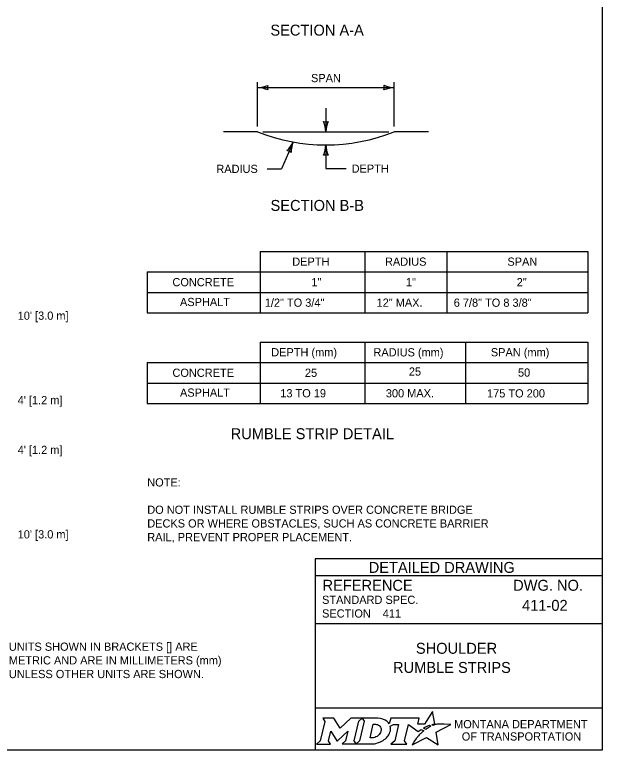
# Model space of a CAD drawing. Extents: x 49991.4 to 50021, y 49987.6 to 50011.4.
# Drawn here: x 50012.45 to 50016.75, y 49987.8 to 49993.18 of the extents above; entities that cross this region are included whole.
import ezdxf

# ---------------------------------------------------------------- set-up
doc = ezdxf.new("R2010")
doc.units = 0
for name, color, linetype in [('Default', 7, 'Continuous'), ('Level 1', 7, 'Continuous'), ('Level 2', 7, 'Continuous'), ('Level 3', 7, 'Continuous'), ('Level 5', 7, 'Continuous')]:
    doc.layers.add(name, color=color, linetype=linetype)

msp = doc.modelspace()

# ---------------------------------------------------------------- linework, layer by layer
at = {"layer": 'Default'}
for points in [[(50015.5126, 49987.9811), (50015.5023, 49987.9867), (50015.5139, 49987.9895), (50015.5255, 49987.9915), (50015.5081, 49988.0816), (50015.4486, 49987.9903), (50015.4013, 49987.9896), (50015.4116, 49988.0337), (50015.2024, 49988.0338), (50015.1923, 49987.9913), (50015.1865, 49987.9996)], [(50014.7056, 49988.0338), (50014.7197, 49988.0104), (50014.6862, 49987.8671), (50014.6605, 49987.8446), (50014.7621, 49987.8446), (50014.7486, 49987.8674), (50014.7648, 49987.9375), (50014.8085, 49987.8685), (50014.8138, 49987.8685), (50014.8889, 49987.938), (50014.8725, 49987.8669), (50014.8478, 49987.8449), (50014.9494, 49987.8449), (50014.9356, 49987.8682), (50014.9688, 49988.0106)], [(50014.9688, 49988.0106), (50014.9941, 49988.0338), (50014.9117, 49988.0338), (50014.8321, 49987.9608), (50014.7876, 49988.0335), (50014.7056, 49988.0338)], [(50015.1077, 49988.0338), (50014.9941, 49988.0338), (50015.0088, 49988.0109), (50014.9749, 49987.8671), (50014.9494, 49987.8449), (50015.06, 49987.8449)], [(50015.1317, 49987.9471), (50015.1305, 49987.939), (50015.1273, 49987.9297), (50015.1231, 49987.9215), (50015.1175, 49987.914), (50015.111, 49987.9071), (50015.1031, 49987.9008), (50015.0948, 49987.8961), (50015.0857, 49987.8922), (50015.0766, 49987.8899), (50015.0674, 49987.889), (50015.0515, 49987.889), (50015.0751, 49987.989), (50015.0911, 49987.989), (50015.0987, 49987.9884), (50015.1063, 49987.9865), (50015.1129, 49987.9835), (50015.119, 49987.9793), (50015.1238, 49987.9743), (50015.1275, 49987.9683), (50015.1302, 49987.9621), (50015.1318, 49987.9547), (50015.1318, 49987.9517), (50015.1317, 49987.9471)], [(50015.3882, 49987.8843), (50015.3729, 49987.8599), (50015.3682, 49987.8524), (50015.3624, 49987.8438), (50015.3601, 49987.8395), (50015.4654, 49987.8926), (50015.5493, 49987.8375), (50015.5362, 49987.9302), (50015.6431, 49987.9886), (50015.5938, 49987.9894), (50015.5637, 49987.9898), (50015.5429, 49987.9901), (50015.5361, 49987.9886), (50015.5312, 49987.9874), (50015.5228, 49987.9851), (50015.5126, 49987.9811)], [(50015.1991, 49987.9747), (50015.2237, 49987.9878), (50015.2606, 49987.9878), (50015.232, 49987.8673), (50015.2045, 49987.8446), (50015.3207, 49987.8446), (50015.3037, 49987.8675), (50015.3319, 49987.9877), (50015.4032, 49987.936), (50015.4243, 49987.9511), (50015.444, 49987.9402)], [(50015.4622, 49987.9535), (50015.4598, 49987.9518), (50015.4415, 49987.9614), (50015.4518, 49987.9671), (50015.4559, 49987.9693), (50015.4645, 49987.9733), (50015.4702, 49987.9759), (50015.4781, 49987.9789), (50015.4854, 49987.9816), (50015.4972, 49987.9742), (50015.4932, 49987.9721), (50015.4886, 49987.9696), (50015.4844, 49987.9674), (50015.4794, 49987.9645), (50015.4775, 49987.9634), (50015.4748, 49987.9618), (50015.4723, 49987.9604), (50015.47, 49987.9588), (50015.4674, 49987.957), (50015.4647, 49987.9552), (50015.4622, 49987.9535)], [(50015.4021, 49987.9004), (50015.4021, 49987.9004)], [(50015.1057, 49987.8522), (50015.1141, 49987.8548), (50015.1271, 49987.8602), (50015.1475, 49987.8712)]]:
    msp.add_lwpolyline(points, dxfattribs=at)
for centre, radius, start, end in [((50015.1308, 49987.9554), 0.0709, 339.5329, 15.8582), ((50015.0868, 49987.9727), 0.1183, 300.9103, 339.1383)]:
    msp.add_arc(centre, radius, start, end, dxfattribs=at)
for centre, major_axis, ratio, start_param, end_param in [((50015.1056, 49987.9864), (0.0834, -0.0037), 0.568097, 0.61298, 1.570796), ((50015.1612, 49987.9937), (0.0361, -0.0295), 0.469099, 1.225588, 1.570796), ((50015.4329, 49987.9305), (-0.0112, -0.0097), 0.021651, 3.157348, 6.283185), ((50015.3952, 49987.8923), (-0.00694, -0.00806), 0.008222, 0, 3.137361), ((50015.4119, 49987.9106), (-0.0098, -0.0102), 0.016458, 3.141593, 6.279097), ((50015.0603, 49987.9932), (0, 0.1484), 0.987302, 3.139398, 3.456847)]:
    msp.add_ellipse(centre, major_axis=major_axis, ratio=ratio, start_param=start_param, end_param=end_param, dxfattribs=at)
at = {"layer": 'Level 1'}
for p, q in [((50014.2284, 49992.3211), (50013.9784, 49992.3211)), ((50015.4784, 49992.3211), (50015.2284, 49992.3211))]:
    msp.add_line(p, q, dxfattribs=at)
msp.add_lwpolyline([(49999.3835, 49998.9992), (50016.7501, 49998.9992), (50016.7501, 49987.7988), (49999.3835, 49987.7988)], close=True, dxfattribs=at)
msp.add_arc((50014.7283, 49993.5894), 1.3633, 248.4841, 291.5159, dxfattribs=at)
at = {"layer": 'Level 2'}
for p, q in [((50014.2469, 49991.4473), (50016.6435, 49991.4473)), ((50014.2469, 49991.4473), (50014.2469, 49990.9973)), ((50015.0139, 49991.4473), (50015.0139, 49990.9973)), ((50015.6139, 49991.4473), (50015.6139, 49990.9973)), ((50016.6435, 49991.4473), (50016.6435, 49990.9973)), ((50013.4219, 49991.2973), (50013.4219, 49990.9973)), ((50013.4219, 49991.2973), (50014.2469, 49991.2973)), ((50014.2469, 49991.2973), (50016.6435, 49991.2973)), ((50014.2469, 49991.2973), (50016.1469, 49991.2973)), ((50014.2469, 49991.2973), (50016.1469, 49991.2973)), ((50013.4219, 49991.1473), (50016.6435, 49991.1473)), ((50014.2469, 49991.1473), (50016.1469, 49991.1473)), ((50013.4219, 49990.9973), (50016.6435, 49990.9973)), ((50014.2469, 49990.9973), (50016.1469, 49990.9973)), ((50014.2469, 49990.7846), (50016.6435, 49990.7846)), ((50014.2469, 49990.7846), (50014.2469, 49990.3346)), ((50015.0139, 49990.7846), (50015.0139, 49990.3346)), ((50015.7508, 49990.7846), (50015.7508, 49990.3346)), ((50016.6435, 49990.7846), (50016.6435, 49990.3346)), ((50013.4219, 49990.6346), (50013.4219, 49990.3346)), ((50013.4219, 49990.6346), (50016.6435, 49990.6346)), ((50013.4219, 49990.4846), (50016.6435, 49990.4846)), ((50013.4219, 49990.3346), (50016.6435, 49990.3346))]:
    msp.add_line(p, q, dxfattribs=at)
at = {"layer": 'Level 3'}
for p, q in [((50014.2284, 49992.3611), (50014.2284, 49992.6849)), ((50015.2284, 49992.3611), (50015.2284, 49992.6849)), ((50014.2284, 49992.6449), (50015.2284, 49992.6449)), ((50014.7284, 49992.4945), (50014.7284, 49992.3211)), ((50014.2683, 49992.3211), (50015.1883, 49992.3211)), ((50014.4888, 49992.2473), (50014.4043, 49992.0508)), ((50014.7284, 49992.2261), (50014.7284, 49992.0527)), ((50014.2988, 49992.0508), (50014.4043, 49992.0508)), ((50014.7284, 49992.0527), (50014.8766, 49992.0527))]:
    msp.add_line(p, q, dxfattribs=at)
for centre, radius, start, end in [((50014.2169, 49992.8776), 0.233, 272.8273, 292.0772), ((50014.2192, 49992.4228), 0.2223, 67.456, 87.6395), ((50014.3566, 49992.6449), 0.0548, 162.1388, 197.8612), ((50015.2376, 49992.8671), 0.2223, 247.456, 267.6395), ((50015.1002, 49992.6449), 0.0548, 342.1388, 17.8612), ((50015.2399, 49992.4122), 0.233, 92.8273, 112.0772), ((50014.7284, 49992.4493), 0.0548, 252.1388, 287.8612), ((50014.4957, 49992.3096), 0.233, 2.8273, 22.0772), ((50014.9505, 49992.312), 0.2223, 157.456, 177.6395), ((50014.2883, 49992.3435), 0.2223, 314.1908, 334.3743), ((50014.7071, 49992.166), 0.233, 159.5621, 178.8119), ((50014.5063, 49992.2353), 0.2223, 337.456, 357.6395), ((50014.9611, 49992.2376), 0.233, 182.8273, 202.0772), ((50014.4382, 49992.1296), 0.0548, 48.8736, 84.5959), ((50014.7284, 49992.0979), 0.0548, 72.1388, 107.8612)]:
    msp.add_arc(centre, radius, start, end, dxfattribs=at)
at = {"layer": 'Level 5'}
for p, q in [((50016.7501, 49989.1988), (50014.6501, 49989.1988)), ((50014.6501, 49989.1988), (50014.6501, 49987.7988)), ((50016.7501, 49989.0738), (50014.6501, 49989.0738)), ((50016.3862, 49988.8587), (50016.3862, 49988.8587)), ((50015.1444, 49988.7993), (50015.1444, 49988.7993)), ((50016.7501, 49988.7238), (50014.6501, 49988.7238)), ((50015.7001, 49988.4747), (50015.7001, 49988.4747)), ((50016.7501, 49988.1057), (50014.6501, 49988.1057))]:
    msp.add_line(p, q, dxfattribs=at)

# ---------------------------------------------------------------- texts
at = {"layer": 'Default'}
for s, p in [('MONTANA DEPARTMENT', (50015.6663, 49987.96)), ('OF TRANSPORTATION', (50015.7225, 49987.87))]:
    msp.add_text(s, height=0.06, dxfattribs=at).set_placement(p)
at = {"layer": 'Level 2'}
for s, height, p in [('SECTION A-A', 0.08, (50014.3224, 49993.0255)), ('SPAN', 0.06, (50014.6197, 49992.6849)), ('RADIUS', 0.06, (50013.9272, 49992.0208)), ('DEPTH', 0.06, (50014.9166, 49992.0227)), ('SECTION B-B', 0.08, (50014.3236, 49991.7436)), ('DEPTH', 0.06, (50014.4824, 49991.3425)), ('RADIUS', 0.06, (50015.1606, 49991.3425)), ('SPAN', 0.06, (50016.0561, 49991.3423)), ('CONCRETE', 0.06, (50013.6061, 49991.1925)), ('1"', 0.06, (50014.6222, 49991.1925)), ('1"', 0.06, (50015.314, 49991.1925)), ('2"', 0.06, (50016.1241, 49991.1923)), ('ASPHALT', 0.06, (50013.6613, 49991.0473)), ('1/2" TO 3/4"', 0.06, (50014.2815, 49991.0425)), ('12" MAX.', 0.06, (50015.0992, 49991.0425)), ('6 7/8" TO 8 3/8"', 0.06, (50015.6634, 49991.0423)), ('DEPTH (mm)', 0.06, (50014.3286, 49990.6798)), ('RADIUS (mm)', 0.06, (50015.0763, 49990.6793)), ('SPAN (mm)', 0.06, (50015.935, 49990.6798)), ('CONCRETE', 0.06, (50013.6061, 49990.5298)), ('25', 0.06, (50014.5751, 49990.5298)), ('25', 0.06, (50015.3353, 49990.5387)), ('50', 0.06, (50016.1335, 49990.5312)), ('ASPHALT', 0.06, (50013.6613, 49990.3846)), ('13 TO 19', 0.06, (50014.3949, 49990.3798)), ('300 MAX.', 0.06, (50015.167, 49990.3798)), ('175 TO 200', 0.06, (50015.9072, 49990.3791)), ('RUMBLE STRIP DETAIL', 0.08, (50014.0319, 49990.0741)), ('NOTE:', 0.06, (50013.4219, 49989.7281)), ('DO NOT INSTALL RUMBLE STRIPS OVER CONCRETE BRIDGE', 0.06, (50013.4219, 49989.5281)), ('DECKS OR WHERE OBSTACLES, SUCH AS CONCRETE BARRIER', 0.06, (50013.4219, 49989.4281)), ('RAIL, PREVENT PROPER PLACEMENT.', 0.06, (50013.4219, 49989.3281)), ('411-02', 0.08, (50016.1635, 49988.8187)), ('411', 0.06, (50015.1444, 49988.7693)), ('UNITS SHOWN IN BRACKETS [] ARE ', 0.06, (50012.4097, 49988.5266)), ('SHOULDER', 0.08, (50015.3868, 49988.5047)), ('METRIC AND ARE IN MILLIMETERS (mm) ', 0.06, (50012.4097, 49988.4266)), ('RUMBLE STRIPS', 0.08, (50015.2193, 49988.3647)), ('UNLESS OTHER UNITS ARE SHOWN.', 0.06, (50012.4097, 49988.3266))]:
    msp.add_text(s, height=height, dxfattribs=at).set_placement(p)
for s, rotation, p in [("10' [3.0 m]", 359.9999, (50012.4743, 49990.9473)), ("4' [1.2 m]", 359.9999, (50012.4743, 49990.3298)), ("4' [1.2 m]", 360, (50012.4743, 49989.9657)), ("10' [3.0 m]", 360, (50012.4743, 49989.3481))]:
    msp.add_text(s, height=0.06, rotation=rotation, dxfattribs=at).set_placement(p)
at = {"layer": 'Level 5'}
for s, height, p in [('DETAILED DRAWING', 0.0799, (50015.0418, 49989.0963)), ('REFERENCE', 0.08, (50014.7037, 49988.9654)), ('DWG. NO.', 0.08, (50016.0979, 49988.9654)), ('STANDARD SPEC.', 0.06, (50014.7004, 49988.8694)), ('SECTION', 0.06, (50014.7004, 49988.7694))]:
    msp.add_text(s, height=height, dxfattribs=at).set_placement(p)

doc.saveas('drawing.dxf')
